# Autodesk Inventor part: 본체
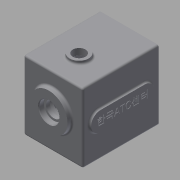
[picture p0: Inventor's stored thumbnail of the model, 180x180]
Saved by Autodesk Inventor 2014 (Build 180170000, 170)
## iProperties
Created: 2016-02
Part Number: 본체
Material: 알루미늄 6061
Document SubType Name: Modeling
Designer: mduedu
Density: 2.71 g/cm^3
Mass: 1515.92 g
Surface Area: 1077.08 cm^2
Volume: 559.381 cm^3
Appearance: 기본값
Author: mduedu
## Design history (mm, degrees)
sketch "스케치1"
  geometry: L1 (-47, -47)-(47, -47); L2 (47, -47)-(47, 63); L3 (47, 63)-(-47, 63); L4 (-47, 63)-(-47, -47); 2 further points
  constraints: 8 end point, 2 parallel, 1 horizontal, 1 midpoint, 1 perpendicular, 1 vertical alignment
  dimensions: "d0" = 94 distance of L2.end L3.end; "d155" = 110 distance of L1.end L2.end; "d156" = 47 distance from line of L1 point (0, 0)
extrude "돌출1" new body sketch "스케치1" distance "d2" = 120; taper "d3" = 0 deg
sketch "스케치3"
  geometry: L1 (47, -47)-(-47, -47) reference; L2 (47, 63)-(47, -47) reference; L3 (-47, 63)-(47, 63) reference; L4 (-47, -47)-(-47, 63) reference; L5 (37, 53)-(37, -37); L6 (37, -37)-(-37, -37); L7 (-37, -37)-(-37, 53); L8 (-37, 53)-(37, 53); 1 further point
  constraints: 8 end point, 3 other
  dimensions: "d226" = 10 distance between parallel lines of L8 L3
extrude "돌출3" cut sketch "스케치3" distance "d11" = 110; taper "d12" = 0 deg
sketch "스케치4"
  geometry: C1 r 21 at (0, 11); 1 further point
  constraints: 1 centre point, 1 vertical alignment
  dimensions: "d13" = 21 radius of C1; "d227" = 11 distance of point (0, 0) C1.centre
extrude "돌출4" join sketch "스케치4" distance "d16" = 7; taper "d17" = 0 deg
sketch "스케치5"
  geometry: C1 r 15 at (0, -20); 1 further point
  constraints: 1 centre point, 1 vertical alignment
  dimensions: "d18" = 15 radius of C1; "d20" = 20 distance of point (0, 0) C1.centre
extrude "돌출5" join sketch "스케치5" distance "d21" = 7; taper "d22" = 0 deg
sketch "스케치6"
  geometry: C1 r 30 at (0, 11); A1 r 21 centre (0, 11) between (8.978, -7.984) and (-8.978, -7.984) reference; 1 further point
  constraints: 1 centre point, 1 coincident
  dimensions: "d228" = 60 diameter of C1
extrude "돌출6" join sketch "스케치6" distance "d25" = 7; taper "d26" = -3 deg
hole "구멍1" diameter "d29" = 35; stored, may be unused: countersink angle "d33" = 90 deg, drill point angle "d35" = 0 deg; dims "d27" = 10, "d28" = 10, "d30" = 6, "d31" = 4, "d32" = 2, "d34" = 10
hole "구멍2" diameter "d38" = 22; stored, may be unused: countersink angle "d42" = 90 deg, drill point angle "d44" = 0 deg; dims "d36" = 10, "d37" = 10, "d39" = 6, "d40" = 4, "d41" = 2, "d43" = 7
hole "구멍3" diameter "d47" = 19; stored, may be unused: countersink angle "d51" = 90 deg, drill point angle "d53" = 0 deg; dims "d45" = 10, "d46" = 10, "d48" = 6, "d49" = 4, "d50" = 2, "d52" = 1
hole "구멍4" diameter "d56" = 32; stored, may be unused: countersink angle "d60" = 90 deg, drill point angle "d62" = 0 deg; dims "d57" = 6, "d58" = 4, "d59" = 2, "d61" = 8, "d220" = 10, "d221" = 10
hole "구멍5" diameter "d65" = 25; stored, may be unused: countersink angle "d69" = 90 deg, drill point angle "d71" = 0 deg; dims "d63" = 10, "d64" = 10, "d66" = 6, "d67" = 4, "d68" = 2, "d70" = 8
fillet "모깎기2" dims "d73" = 0.3
fillet "모깎기3" dims "d74" = 2
chamfer "모따기1" distance "d75" = 1; stored, may be unused: second distance "d76" = 2, angle "d77" = 45 deg
fillet "모깎기4" dims "d78" = 3
fillet "모깎기23" dims "d240" = 1
fillet "모깎기20" dims "d229" = 3
sketch "스케치23"
  geometry: L1 (-37, 53)-(37, 53) reference; L2 (37, 53)-(37, -37) reference; L3 (37, -37)-(-37, -37) reference; L4 (-37, -37)-(-37, 53) reference; L5 (44, -47)-(-44, -47) reference; L6 (47, 60)-(47, -44) reference; L7 (-44, 63)-(44, 63) reference; L8 (-47, -44)-(-47, 60) reference; C1 r 10 at (-37, 53); C2 r 10 at (37, 53); C3 r 10 at (-37, -37); C4 r 10 at (37, -37); A1 r 3 centre (-44, -44) between (-47, -44) and (-44, -47) reference; A2 r 3 centre (44, -44) between (44, -47) and (47, -44) reference; A3 r 3 centre (44, 60) between (47, 60) and (44, 63) reference; A4 r 3 centre (-44, 60) between (-44, 63) and (-47, 60) reference; 1 further point
  constraints: 4 centre point, 4 coincident, 3 equal radius
  dimensions: "d230" = 20 diameter of C1
extrude "돌출22" join sketch "스케치23" stored distance "d235" = 10; taper "d236" = 0 deg
fillet "모깎기21" dims "d237" = 3
node "작업 평면1"
fillet "모깎기22" dims "d239" = 1
sketch "스케치12"
  geometry: A1 r 10 centre (-37, 53) between (-34.692, 43.27) and (-27.27, 50.692) reference; A2 r 10 centre (37, 53) between (27.27, 50.692) and (34.692, 43.27) reference; A3 r 10 centre (37, -37) between (34.692, -27.27) and (27.27, -34.692) reference; A4 r 10 centre (-37, -37) between (-27.27, -34.692) and (-34.692, -27.27) reference; 5 further points
  constraints: 4 coincident
hole "구멍6" sketch "스케치12" at (-37, 53), (37, 53), (37, -37), (-37, -37) diameter "d122" = 3.242; stored, may be unused: countersink angle "d126" = 90 deg, drill point angle "d128" = 120 deg; dims "d123" = 7, "d124" = 4, "d125" = 2, "d127" = 9
sketch "스케치20"
  geometry: L1 (44, 0)-(-44, 0) reference; L2 (44, -120)-(-44, -120) reference; L3 (0, 0)-(0, -120); L4 (-44, -120)-(-44, 0) reference; L5 (44, 0)-(44, -120) reference; C1 r 10 at (0, -79)
  constraints: 2 end point, 1 centre point, 1 midpoint, 1 point on line
  dimensions: "d189" = 20 diameter of C1; "d190" = 41 distance from line of C1.centre L2
extrude "돌출19" cut sketch "스케치20" stored distance "d191" = 10; taper "d192" = 0 deg
sketch "스케치18"
  geometry: C1 r 15 at (0, -79); C2 r 10 at (0, -79) reference; 1 further point
  constraints: 1 centre point, 1 concentric
  dimensions: "d174" = 30 diameter of C1
extrude "돌출17" join sketch "스케치18" distance "d175" = 5; taper "d176" = 0 deg
fillet "모깎기16" dims "d177" = 3
sketch "스케치19"
  geometry: C1 r 15 at (24.351, 79); C2 r 10 at (24.351, 79) reference; 1 further point
  constraints: 1 centre point, 1 concentric
  dimensions: "d178" = 30 diameter of C1
extrude "돌출18" cut sketch "스케치19" distance "d181" = 5; taper "d182" = 0 deg
chamfer "모따기5" distance "d183" = 1; stored, may be unused: second distance "d184" = 2, angle "d185" = 45 deg
fillet "모깎기24" dims "d242" = 3, "d243" = 3
sketch "스케치24"
  geometry: L1 (-95, 67)-(-25, 67); L2 (-25, 67)-(-25, 37); L3 (-25, 37)-(-95, 37); L4 (-95, 37)-(-95, 67); L5 (0, 0)-(0, 104) reference; L6 (-95, 52)-(-25, 52); L7 (-60, 67)-(-60, 37); A1 r 15 centre (-95, 52) between (-95, 37) and (-95, 67); A2 r 15 centre (-25, 52) between (-25, 67) and (-25, 37); A3 r 15 centre (-25, 52) between (-25, 37) and (-25, 67); A4 r 15 centre (-95, 52) between (-95, 67) and (-95, 37); 2 further points
  constraints: 12 end point, 8 point on circle, 5 midpoint, 4 centre point, 2 parallel, 2 perpendicular, 1 horizontal, 1 horizontal alignment
  dimensions: "d244" = 60 distance between parallel lines of L7 L5; "d245" = 100 dimension on A2 A1; "d246" = 30 distance between parallel lines of L3 L1
extrude "돌출23" join sketch "스케치24" distance "d247" = 3; taper "d248" = 0 deg
fillet "모깎기25" dims "d249" = 3
sketch "스케치25"
  geometry: L1 (-25, 67)-(-95, 67) reference; L2 (-95, 37)-(-25, 37) reference; A1 r 15 centre (-95, 52) between (-95, 67) and (-95, 37) reference; A2 r 15 centre (-25, 52) between (-25, 37) and (-25, 67) reference; 3 further points
  constraints: 1 horizontal alignment, 1 midpoint, 1 vertical alignment, 1 other
feature "엠보싱3" sketch "스케치25" dims "d250" = 0.5, "d251" = 0
sketch "스케치26"
  geometry: L1 (14.367, 127)-(73.633, 127) reference; L2 (0, 0)-(88, 0) reference; L3 (88, 120)-(0, 120) reference; 5 further points
  constraints: 3 vertical alignment, 2 midpoint
  dimensions: "d252" = 35 distance from line of point (44, 35) L2; "d253" = 35 distance from line of point (44, 85) L3; "d254" = 50 distance of point (44, 35) point (44, 85) (derived)
hole "구멍8" sketch "스케치26" at (44, 85), (44, 35) diameter "d255" = 6.647; stored, may be unused: countersink angle "d259" = 90 deg, drill point angle "d261" = 118 deg; dims "d256" = 6, "d257" = 4, "d258" = 2, "d260" = 8
node "솔리드1"
node "투영된 루프1"
node "투영된 루프4"
node "투영된 루프5"
node "투영된 루프6"
